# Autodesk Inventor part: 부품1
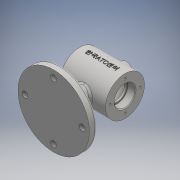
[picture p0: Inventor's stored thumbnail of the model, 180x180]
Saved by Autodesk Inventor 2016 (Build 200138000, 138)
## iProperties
Created: 2018-12
Part Number: 부품1
Material: Generic
Document SubType Name: Modeling
Designer: Administrator
Density: 1 g/cm^3
Appearance: Default
Author: Administrator
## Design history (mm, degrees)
sketch "스케치1"
  geometry: C1 r 30 at (0, 0); 1 further point
  constraints: 1 centre point, 1 coincident
  dimensions: "d0" = 60 diameter of C1
extrude "돌출1" new body sketch "스케치1" stored distance "d1" = 70; taper "d2" = 0 deg
sketch "스케치2" dims "d13" = 0, "d28" = 0
  geometry: L1 (-35, 30)-(-35, -30) reference; L2 (-35, 16)-(-23.3, 16); L3 (-23, 15.7)-(-23, 14); L4 (-23, 14)-(-20, 14); L5 (-20, 14)-(-20, 22); L6 (-17, 25)-(17, 25); L7 (20, 22)-(20, 14); L8 (20, 14)-(23, 14); L9 (23, 14)-(23, 15.7); L10 (23.3, 16)-(35, 16); L11 (-35, 16)-(-35, 0); L12 (35, -30)-(35, 30) reference; L13 (35, 0)-(-35, 0); L14 (35, 16)-(35, 0); A1 r 3 centre (-17, 22) between (-17, 25) and (-20, 22); A2 r 3 centre (17, 22) between (20, 22) and (17, 25); A3 r 0.3 centre (-23.3, 15.7) between (-23, 15.7) and (-23.3, 16); A4 r 0.3 centre (23.3, 15.7) between (23.3, 16) and (23, 15.7); 9 further points
  constraints: 24 end point, 13 point on line, 8 point on circle, 8 tangent, 6 perpendicular, 5 horizontal, 4 centre point, 3 vertical, 2 equal radius, 2 midpoint, 1 collinear, 8 other
  dimensions: "d3" = 12 distance of L2.start point (-23, 16); "d4" = 32 diameter of L2 L13; "d5" = 3 distance of point (-23, 14) L4.end; "d6" = 28 diameter of L4 L13; "d7" = 40 distance of point (-20, 25) point (20, 25); "d8" = 50 diameter of L6 L13; "d9" = 3 distance of L7.end point (23, 14); "d10" = 28 diameter of L8 L13; "d11" = 32 diameter of L10 L13; "d12" = 3 radius of A1; "d69" = 0.3 radius of A3
revolve "회전1" sketch "스케치2" stored, may be unused: angle "d14" = 90 deg
chamfer "모따기1" distance "d15" = 1; stored, may be unused: second distance "d16" = 2, angle "d17" = 45 deg
node "작업 평면1"
sketch "스케치3"
  geometry: C1 r 10 at (0, 0); 1 further point
  constraints: 1 centre point, 1 coincident
  dimensions: "d19" = 20 diameter of C1
extrude "돌출2" join sketch "스케치3" stored distance "d20" = 70; taper "d21" = 0 deg
sketch "스케치4"
  geometry: C1 r 5 at (0, 0); 1 further point
  constraints: 1 centre point, 1 coincident
  dimensions: "d22" = 10 diameter of C1
extrude "돌출3" cut sketch "스케치4" stored distance "d23" = 70; taper "d24" = 0 deg
chamfer "모따기2" distance "d25" = 1; stored, may be unused: second distance "d26" = 2, angle "d27" = 45 deg
sketch "스케치5"
  geometry: L1 (0, 0)-(-75, 0); L2 (-75, -55)-(-75, 55); L3 (-75, -55)-(-64, -55); L4 (-64, -55)-(-52.478, -12); L5 (-52.478, -12)-(-52.478, 0); L6 (-75, 0)-(-52.478, 0)
  constraints: 12 end point, 2 coincident, 2 horizontal, 1 collinear, 1 midpoint, 1 perpendicular, 1 point on line, 1 vertical
  dimensions: "d29" = 75 distance of L1.start L1.end; "d30" = 110 distance of L2.start L2.end; "d31" = 11 distance of L2.start L3.end; "d34" = 75 deg angle of L3 L4; "d35" = 12 distance of L4.end L5.end
revolve "회전2" sketch "스케치5" stored, may be unused: angle "d36" = 90 deg
sketch "스케치6"
  geometry: C1 r 12 at (0, 0); 1 further point
  constraints: 1 centre point, 1 coincident
  dimensions: "d37" = 24 diameter of C1
extrude "돌출4" join sketch "스케치6" stored distance "d38" = 70; taper "d39" = 0 deg
fillet "모깎기1" dims "d40" = 3
sketch "스케치7"
  geometry: C1 r 5 at (0, 0) reference; C2 r 4.5 at (-44, 0); C3 r 4.5 at (0, 44); C4 r 4.5 at (44, 0); C5 r 4.5 at (0, -44); A1 r 44 centre (0, 0) between (-44, 0) and (0, 44); 1 further point
  constraints: 5 centre point, 4 point on circle, 1 coincident
  dimensions: "d41" = 88 diameter of A1; "d42" = 9 diameter of C2; "d43" = 9 diameter of C3; "d44" = 9 diameter of C4; "d45" = 9 diameter of C5
extrude "돌출5" cut sketch "스케치7" distance "d46" = 10; taper "d47" = 0 deg
sketch "스케치8"
  geometry: C1 r 5 at (0, -44) reference; C2 r 7 at (-44, -44); C3 r 7 at (0, 0); C4 r 7 at (44, -44); C5 r 7 at (0, -88); A1 r 44 centre (0, -44) between (-44, -44) and (0, 0); 1 further point
  constraints: 5 centre point, 4 point on circle, 1 coincident
  dimensions: "d48" = 88 diameter of A1; "d49" = 14 diameter of C2; "d50" = 14 diameter of C3; "d51" = 14 diameter of C4; "d52" = 14 diameter of C5
extrude "돌출6" cut sketch "스케치8" distance "d53" = 10; taper "d54" = 0 deg
fillet "모깎기2" dims "d63" = 3
node "작업 평면2"
sketch "스케치10"
  geometry: L1 (-35, 30)-(-35, -30) reference; 2 further points
  constraints: 1 other
  dimensions: "d65" = 35 distance from line of L1 point (0, 0); "d66" = 30 vertical distance of L1.start point (0, 0)
feature "엠보싱1" sketch "스케치10" dims "d3" = 12, "d4" = 32, "d5" = 3, "d6" = 28, "d7" = 40, "d8" = 50, "d9" = 3, "d10" = 28, "d11" = 32, "d12" = 3, "d13" = 0, "d28" = 0, "d67" = 0.5, "d68" = 0, "d69" = 0.3
sketch "스케치11"
  geometry: A1 r 23 centre (0, 0) between (0, 23) and (-23, 0); 3 further points
  constraints: 4 point on circle, 1 centre point, 1 coincident
  dimensions: "d70" = 46 diameter of A1
hole "구멍2" sketch "스케치11" at (0, 23), (-23, 0), (0, -23), (23, 0) diameter "d71" = 3.242; stored, may be unused: countersink angle "d75" = 90 deg, drill point angle "d77" = 118 deg; dims "d72" = 8, "d73" = 4, "d74" = 2, "d76" = 10
node "솔리드1"
mirror "대칭2"
other parameters: "d18" = 37, "d32" = 75 deg
